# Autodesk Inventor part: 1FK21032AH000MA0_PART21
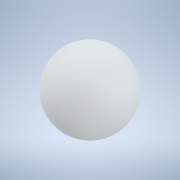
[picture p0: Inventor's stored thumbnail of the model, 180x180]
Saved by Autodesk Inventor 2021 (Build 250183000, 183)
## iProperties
Created: 2025-04
Part Number: 1FK21032AH000MA0_PART21
Material: Generic
Catalog Web Link: www.3dfindit.com
Description: -Servo synchronous motor
Document SubType Name: Modeling
Designer: psAdmin
Mass: 0.113097 g
Surface Area: 1.13097 cm^2
Volume: 0.113097 cm^3
Density: 1 g/cm^3
Appearance: PSOLRGB-212-217-219
Category: PARTsolutions
Title: 1FK21032AH000MA0_PART21
Author: Cadenas PARTsolutions
Comments: Servo synchronous motor
Sending System: PARTsolutions
Preprocessor: ST-DEVELOPER v19.3
PSOL_IDENT_0: {$CADENAS_DATA/23d-libs/siemens_ag/_cat_/45/10/1fk21032ah000ma0.prj},216 {VTYP=3D},{NB=1FK21032AH000
PSOL_IDENT_1: MA0_PART21},{LINA=1FK21032AH000MA0_PART21},{NN=1FK21032AH000MA0_PART21},{NOPRJ=TRUE},{DATE=19.08.202
PSOL_IDENT_2: 5 14:00:35},{GEOMDATE=30.07.2025 02:02:03},{VERSION=},{LINEID=10},{WBVAR=},{WBNUMERIC=}  {NB=1FK2103
PSOL_IDENT_3: 2AH000MA0_PART21},{LINA=1FK21032AH000MA0_PART21},{KT=DUMMY},{PREVIEW=../../../_pool_/14/8e/p_d211_xx
PSOL_IDENT_4: _00426j.png},{DESCSHORT=SIMOTICS S-1FK2 HD, SINAMICS S210 3AC 400V-480V, 0.59 Nm, 4500 rpm},{DESCLON
PSOL_IDENT_5: G=SIMOTICS S-1FK2 HD servo motor M0=0.64 Nm; PN = 0.28 kW at nN=4500 rpm (380-480 V); PN = 0.167 kW
PSOL_IDENT_6: at nN=2500 rpm (200-240 V); degree of protection IP64; cylindrical shaft D14 x 30 mm; absolute encod
PSOL_IDENT_7: er 22-bit + 12-bit multiturn (encoder AM22DQC); with OCC interface; plug size M17, rotatable; SIMOTI
PSOL_IDENT_8: CS S-1FK2 servomotorfor a wide range of uses in industrial environments. SIMOTICS S‑1FK2 servomotors
PSOL_IDENT_9: are compact synchronous motors with a high dynamic performance that set themselves apart as a resul
PSOL_IDENT_10: t of their high power density, degree of protection and overload capability. The motors are availabl
PSOL_IDENT_11: e in two variants: as High Dynamic variant (highest dynamic performance as a result of the low intri
PSOL_IDENT_12: nsic moment of inertia for applications demanding a high dynamic performance with low moved masses)
PSOL_IDENT_13: - and as Compact variant (precise and stable closed-loop control for medium up to large moved masses
PSOL_IDENT_14: as a result of a medium intrinsic moment of inertia). SIMOTICSS‑1FK2 servomotors fully exploit thei
PSOL_IDENT_15: r strengths in a system with the SINAMICSS210 frequency converter and simple connection using the on
PSOL_IDENT_16: e cable connection (OCC). Advantages include the short control and positioning times, fast and preci
PSOL_IDENT_17: se correction of disturbing quantities as well as stable control with a high dynamic performance. Th
PSOL_IDENT_18: e servo motors can be configured to address a wide range of requirements. For example with and witho
PSOL_IDENT_19: ut holding brake, IP64 or IP65 degree of protection, singleturn or multiturn absolute encoders - to
PSOL_IDENT_20: name just a few. Further, the servomotors are available in different shaft heights extending from 20
PSOL_IDENT_21: to 100. A shaft sealing ring is available to achieve an IP65 degree of protection and for subsequen
PSOL_IDENT_22: t mounting at the motor or as spare part. SIMOTICS - the optimum motor for each and every motion con
PSOL_IDENT_23: trol application.},{INTNO=195125335004},{SUPPLIERALTNO=1FK2103-2AH00-0MA0},{MANUID=1FK21032AH000MA0}
PSOL_IDENT_24: ,{MANUNAME=Siemens},{MANUTYPEDESC=SYNCHRONOUS MOTOR 1FK2 HD 0,64 NM},{AAU732=SIMOTICS},{AAO057=S-1FK
PSOL_IDENT_25: 2},{AAU734=SIMOTICS S-1FK2 HD servo motor M0=0.64 Nm; PN = 0.28 kW at nN=4500 rpm (380-480 V); PN =
PSOL_IDENT_26: 0.167 kW at nN=2500 rpm (200-240 V); degree of protection IP64; cylindrical shaft D14 x 30 mm; absol
PSOL_IDENT_27: ute encoder 22-bit + 12-bit multiturn (encoder AM22DQC); with OCC interface; plug size M17, rotatabl
PSOL_IDENT_28: e;},{AAW338=SYNCHRONOUS MOTOR 1FK2 HD 0,64 NM},{AAO742=SIMOTICS},{AAO663=4034106444624},{NOCUPEROU=1
PSOL_IDENT_29: },{PRICEQUANTITY=1},{QUANTITYMIN=1},{QUANTITYINT=1},{CTN=85015100},{COO=RO},{AAO676=1FK2103-2AH00-0M
PSOL_IDENT_30: A0},{AAO677=Siemens AG},{ORDERUNIT=C62},{CONTENTUNIT=C62}
NB: 1FK21032AH000MA0_PART21
NT: Servo synchronous motor
NBSYN: $MANUID._PART21
LINA: 1FK21032AH000MA0_PART21
CATALOG: SIEMENS
PREVIEW: ../../../_pool_/14/8e/p_d211_xx_00426j.png
DESCSHORT: SIMOTICS S-1FK2 HD, SINAMICS S210 3AC 400V-480V, 0.59 Nm, 4500 rpm
DESCLONG: SIMOTICS S-1FK2 HD servo motor M0=0.64 Nm; PN = 0.28 kW at nN=4500 rpm (380-480 V); PN = 0.167 kW at nN=2500 rpm (200-240 V); degree of protection IP64; cylindr
INTNO: 195125335004
SUPPLIERALTNO: 1FK2103-2AH00-0MA0
MANUID: 1FK21032AH000MA0
MANUNAME: Siemens
MANUTYPEDESC: SYNCHRONOUS MOTOR 1FK2 HD 0,64 NM
AAU732: SIMOTICS
AAO057: S-1FK2
AAU734: SIMOTICS S-1FK2 HD servo motor M0=0.64 Nm; PN = 0.28 kW at nN=4500 rpm (380-480 V); PN = 0.167 kW at nN=2500 rpm (200-240 V); degree of protection IP64; cylindr
AAW338: SYNCHRONOUS MOTOR 1FK2 HD 0,64 NM
AAO742: SIMOTICS
AAO663: 4034106444624.0
NOCUPEROU: 1
PRICEQUANTITY: 1
QUANTITYMIN: 1
QUANTITYINT: 1
CTN: 85015100
COO: RO
ARTICLENO: 1FK21032AH000MA0_PART21
BOMINFO: 1FK21032AH000MA0_PART21
CREATOR: CADENAS GmbH
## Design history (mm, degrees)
feature "2025_04_17_15_00_20_0760"
body "Solid1"
